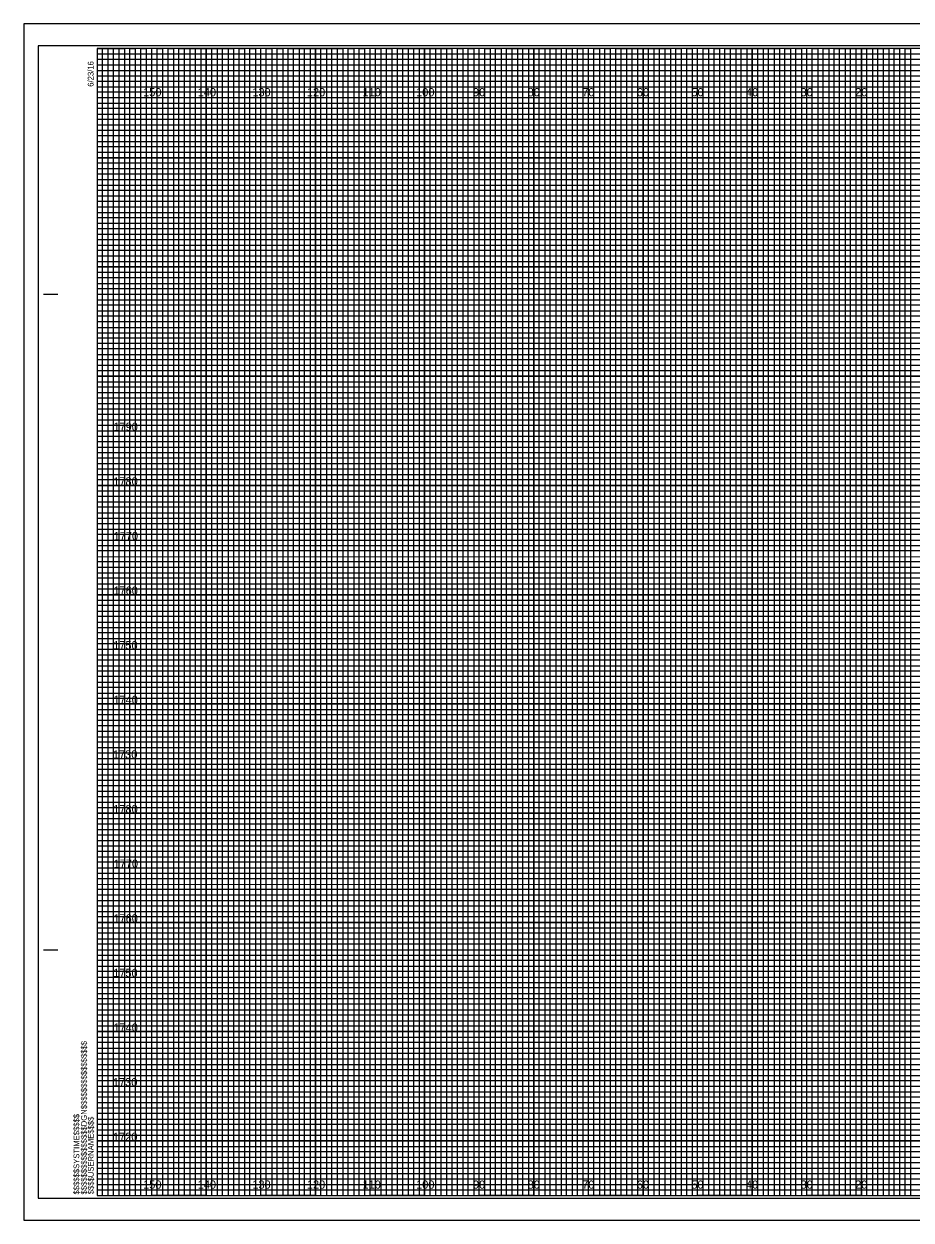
# Model space of a CAD drawing. Extents: x -15 to 323, y -5 to 6170.
# Drawn here: x -13.4 to 149.1, y 1095.5 to 1314.5 of the extents above; entities that cross this region are included whole.
import ezdxf

# ---------------------------------------------------------------- set-up
doc = ezdxf.new("R2010")
doc.units = 0
for name, color, linetype in [('Prop XS DDE', 7, 'Continuous'), ('Prop XS DDE Slope Text', 7, 'Continuous'), ('Prop XS DDE Text', 7, 'Continuous'), ('Prop XS Earthwork Shape', 7, 'Continuous'), ('Prop XS Noise Wall', 7, 'Continuous'), ('Prop XS Retaining Wall', 7, 'Continuous'), ('Prop XS Station Labels', 7, 'Continuous'), ('Scratch_Level_3', 7, 'Continuous'), ('Scratch_Level_7', 7, 'Continuous'), ('Scratch_Level_8', 7, 'Continuous'), ('Sheet Cross Section Grid Minor 1 CELL', 7, 'Continuous')]:
    doc.layers.add(name, color=color, linetype=linetype)

msp = doc.modelspace()

# ---------------------------------------------------------------- linework, layer by layer
at = {"layer": 'Prop XS DDE'}
msp.add_lwpolyline([(-13.4, 1095.5), (323.3, 1095.5), (323.3, 1314.5), (-13.4, 1314.5)], close=True, dxfattribs=at)
at = {"layer": 'Prop XS DDE Slope Text'}
msp.add_lwpolyline([(-10.8, 1099.5), (322.4, 1099.5), (322.4, 1310.5), (-10.8, 1310.5)], close=True, dxfattribs=at)
at = {"layer": 'Prop XS DDE Text'}
for p, q in [((10, 1100), (10, 1310)), ((20, 1100), (20, 1310)), ((30, 1100), (30, 1310)), ((40, 1100), (40, 1310)), ((50, 1100), (50, 1310)), ((60, 1100), (60, 1310)), ((70, 1100), (70, 1310)), ((80, 1100), (80, 1310)), ((90, 1100), (90, 1310)), ((100, 1100), (100, 1310)), ((110, 1100), (110, 1310)), ((120, 1100), (120, 1310)), ((130, 1100), (130, 1310)), ((140, 1100), (140, 1310)), ((0, 1300), (320, 1300)), ((0, 1290), (320, 1290)), ((0, 1280), (320, 1280)), ((0, 1270), (320, 1270)), ((0, 1260), (320, 1260)), ((0, 1250), (320, 1250)), ((0, 1240), (320, 1240)), ((0, 1230), (320, 1230)), ((0, 1220), (320, 1220)), ((0, 1210), (320, 1210)), ((0, 1200), (320, 1200)), ((0, 1190), (320, 1190)), ((0, 1180), (320, 1180)), ((0, 1170), (320, 1170)), ((0, 1160), (320, 1160)), ((0, 1150), (320, 1150)), ((0, 1140), (320, 1140)), ((0, 1130), (320, 1130)), ((0, 1120), (320, 1120)), ((0, 1110), (320, 1110))]:
    msp.add_line(p, q, dxfattribs=at)
at = {"layer": 'Prop XS Earthwork Shape'}
for p, q in [((10, 1310), (0, 1310)), ((10, 1100), (10, 1310)), ((30, 1310), (20, 1310)), ((20, 1310), (20, 1100)), ((30, 1100), (30, 1310)), ((50, 1310), (40, 1310)), ((40, 1310), (40, 1100)), ((50, 1100), (50, 1310)), ((70, 1310), (60, 1310)), ((60, 1310), (60, 1100)), ((70, 1100), (70, 1310)), ((90, 1310), (80, 1310)), ((80, 1310), (80, 1100)), ((90, 1100), (90, 1310)), ((110, 1310), (100, 1310)), ((100, 1310), (100, 1100)), ((110, 1100), (110, 1310)), ((130, 1310), (120, 1310)), ((120, 1310), (120, 1100)), ((130, 1100), (130, 1310)), ((150, 1310), (140, 1310)), ((140, 1310), (140, 1100)), ((20, 1100), (10, 1100)), ((40, 1100), (30, 1100)), ((60, 1100), (50, 1100)), ((80, 1100), (70, 1100)), ((100, 1100), (90, 1100)), ((120, 1100), (110, 1100)), ((140, 1100), (130, 1100))]:
    msp.add_line(p, q, dxfattribs=at)
for points in [[(0, 1300), (320, 1300), (320, 1290), (0, 1290)], [(0, 1280), (320, 1280), (320, 1270), (0, 1270)], [(0, 1260), (320, 1260), (320, 1250), (0, 1250)], [(0, 1240), (320, 1240), (320, 1230), (0, 1230)], [(0, 1220), (320, 1220), (320, 1210), (0, 1210)], [(0, 1200), (320, 1200), (320, 1190), (0, 1190)], [(0, 1180), (320, 1180), (320, 1170), (0, 1170)], [(0, 1160), (320, 1160), (320, 1150), (0, 1150)], [(0, 1140), (320, 1140), (320, 1130), (0, 1130)], [(0, 1120), (320, 1120), (320, 1110), (0, 1110)]]:
    msp.add_lwpolyline(points, dxfattribs=at)
at = {"layer": 'Prop XS Noise Wall'}
for p, q in [((-9.8, 1265), (-7.3, 1265)), ((-9.7, 1265), (-7.2, 1265)), ((-9.8, 1145), (-7.3, 1145)), ((-9.7, 1145), (-7.2, 1145)), ((0, 1100), (0, 1100)), ((0, 1100), (0, 1100)), ((0, 1100), (0, 1100)), ((0, 1100), (0, 1100)), ((0, 1100), (0, 1100)), ((0, 1100), (0, 1100)), ((0, 1100), (0, 1100))]:
    msp.add_line(p, q, dxfattribs=at)
msp.add_lwpolyline([(320, 1310), (0, 1310), (0, 1100), (320, 1100)], close=True, dxfattribs=at)
at = {"layer": 'Prop XS Retaining Wall'}
for points in [[(0, 1100), (1, 1100), (1, 1310), (2, 1310), (2, 1100)], [(2, 1100), (3, 1100), (3, 1310), (4, 1310), (4, 1100)], [(5, 1100), (6, 1100), (6, 1310), (7, 1310), (7, 1100)], [(7, 1100), (8, 1100), (8, 1310), (9, 1310), (9, 1100)], [(10, 1100), (11, 1100), (11, 1310), (12, 1310), (12, 1100)], [(12, 1100), (13, 1100), (13, 1310), (14, 1310), (14, 1100)], [(15, 1100), (16, 1100), (16, 1310), (17, 1310), (17, 1100)], [(17, 1100), (18, 1100), (18, 1310), (19, 1310), (19, 1100)], [(20, 1100), (21, 1100), (21, 1310), (22, 1310), (22, 1100)], [(22, 1100), (23, 1100), (23, 1310), (24, 1310), (24, 1100)], [(25, 1100), (26, 1100), (26, 1310), (27, 1310), (27, 1100)], [(27, 1100), (28, 1100), (28, 1310), (29, 1310), (29, 1100)], [(30, 1100), (31, 1100), (31, 1310), (32, 1310), (32, 1100)], [(32, 1100), (33, 1100), (33, 1310), (34, 1310), (34, 1100)], [(35, 1100), (36, 1100), (36, 1310), (37, 1310), (37, 1100)], [(37, 1100), (38, 1100), (38, 1310), (39, 1310), (39, 1100)], [(40, 1100), (41, 1100), (41, 1310), (42, 1310), (42, 1100)], [(42, 1100), (43, 1100), (43, 1310), (44, 1310), (44, 1100)], [(45, 1100), (46, 1100), (46, 1310), (47, 1310), (47, 1100)], [(47, 1100), (48, 1100), (48, 1310), (49, 1310), (49, 1100)], [(50, 1100), (51, 1100), (51, 1310), (52, 1310), (52, 1100)], [(52, 1100), (53, 1100), (53, 1310), (54, 1310), (54, 1100)], [(55, 1100), (56, 1100), (56, 1310), (57, 1310), (57, 1100)], [(57, 1100), (58, 1100), (58, 1310), (59, 1310), (59, 1100)], [(60, 1100), (61, 1100), (61, 1310), (62, 1310), (62, 1100)], [(62, 1100), (63, 1100), (63, 1310), (64, 1310), (64, 1100)], [(65, 1100), (66, 1100), (66, 1310), (67, 1310), (67, 1100)], [(67, 1100), (68, 1100), (68, 1310), (69, 1310), (69, 1100)], [(70, 1100), (71, 1100), (71, 1310), (72, 1310), (72, 1100)], [(72, 1100), (73, 1100), (73, 1310), (74, 1310), (74, 1100)], [(75, 1100), (76, 1100), (76, 1310), (77, 1310), (77, 1100)], [(77, 1100), (78, 1100), (78, 1310), (79, 1310), (79, 1100)], [(80, 1100), (81, 1100), (81, 1310), (82, 1310), (82, 1100)], [(82, 1100), (83, 1100), (83, 1310), (84, 1310), (84, 1100)], [(85, 1100), (86, 1100), (86, 1310), (87, 1310), (87, 1100)], [(87, 1100), (88, 1100), (88, 1310), (89, 1310), (89, 1100)], [(90, 1100), (91, 1100), (91, 1310), (92, 1310), (92, 1100)], [(92, 1100), (93, 1100), (93, 1310), (94, 1310), (94, 1100)], [(95, 1100), (96, 1100), (96, 1310), (97, 1310), (97, 1100)], [(97, 1100), (98, 1100), (98, 1310), (99, 1310), (99, 1100)], [(100, 1100), (101, 1100), (101, 1310), (102, 1310), (102, 1100)], [(102, 1100), (103, 1100), (103, 1310), (104, 1310), (104, 1100)], [(105, 1100), (106, 1100), (106, 1310), (107, 1310), (107, 1100)], [(107, 1100), (108, 1100), (108, 1310), (109, 1310), (109, 1100)], [(110, 1100), (111, 1100), (111, 1310), (112, 1310), (112, 1100)], [(112, 1100), (113, 1100), (113, 1310), (114, 1310), (114, 1100)], [(115, 1100), (116, 1100), (116, 1310), (117, 1310), (117, 1100)], [(117, 1100), (118, 1100), (118, 1310), (119, 1310), (119, 1100)], [(120, 1100), (121, 1100), (121, 1310), (122, 1310), (122, 1100)], [(122, 1100), (123, 1100), (123, 1310), (124, 1310), (124, 1100)], [(125, 1100), (126, 1100), (126, 1310), (127, 1310), (127, 1100)], [(127, 1100), (128, 1100), (128, 1310), (129, 1310), (129, 1100)], [(130, 1100), (131, 1100), (131, 1310), (132, 1310), (132, 1100)], [(132, 1100), (133, 1100), (133, 1310), (134, 1310), (134, 1100)], [(135, 1100), (136, 1100), (136, 1310), (137, 1310), (137, 1100)], [(137, 1100), (138, 1100), (138, 1310), (139, 1310), (139, 1100)], [(140, 1100), (141, 1100), (141, 1310), (142, 1310), (142, 1100)], [(142, 1100), (143, 1100), (143, 1310), (144, 1310), (144, 1100)], [(145, 1100), (146, 1100), (146, 1310), (147, 1310), (147, 1100)], [(147, 1100), (148, 1100), (148, 1310), (149, 1310), (149, 1100)]]:
    msp.add_lwpolyline(points, dxfattribs=at)
at = {"layer": 'Prop XS Station Labels'}
for points in [[(0, 1310), (5, 1310), (5, 1100), (15, 1100), (15, 1310), (25, 1310), (25, 1100), (35, 1100), (35, 1310), (45, 1310), (45, 1100), (55, 1100), (55, 1310), (65, 1310), (65, 1100), (75, 1100), (75, 1310), (85, 1310), (85, 1100), (95, 1100), (95, 1310), (105, 1310), (105, 1100), (115, 1100), (115, 1310), (125, 1310), (125, 1100), (135, 1100), (135, 1310), (145, 1310), (145, 1100), (155, 1100)], [(0, 1305), (275, 1305)], [(0, 1285), (320, 1285), (320, 1295), (0, 1295)], [(0, 1265), (320, 1265), (320, 1275), (0, 1275)], [(0, 1245), (320, 1245), (320, 1255), (0, 1255)], [(0, 1225), (320, 1225), (320, 1235), (0, 1235)], [(0, 1205), (320, 1205), (320, 1215), (0, 1215)], [(0, 1185), (320, 1185), (320, 1195), (0, 1195)], [(0, 1165), (320, 1165), (320, 1175), (0, 1175)], [(0, 1145), (320, 1145), (320, 1155), (0, 1155)], [(0, 1125), (320, 1125), (320, 1135), (0, 1135)], [(0, 1105), (320, 1105), (320, 1115), (0, 1115)]]:
    msp.add_lwpolyline(points, dxfattribs=at)
at = {"layer": 'Scratch_Level_7'}
for p, q in [((323.3, 1314.5), (-13.4, 1314.5)), ((-13.4, 1314.5), (-13.4, 1095.5)), ((-13.4, 1095.5), (323.3, 1095.5))]:
    msp.add_line(p, q, dxfattribs=at)
at = {"layer": 'Sheet Cross Section Grid Minor 1 CELL'}
for p, q in [((0, 1309), (260, 1309)), ((260, 1307.98), (0, 1307.98)), ((0, 1307.98), (0, 1307)), ((0, 1307), (260, 1307)), ((260, 1305.89), (0, 1305.89)), ((0, 1305.89), (0, 1304)), ((0, 1304), (320, 1304))]:
    msp.add_line(p, q, dxfattribs=at)
for points in [[(0, 1303), (270, 1303), (320, 1303), (320, 1302), (0, 1302)], [(0, 1301), (320, 1301), (320, 1299), (0, 1299)], [(0, 1298), (320, 1298), (320, 1297), (0, 1296.98)], [(0, 1296), (320, 1296), (320, 1294), (0, 1294)], [(0, 1293), (320, 1293), (320, 1292), (0, 1292)], [(0, 1291), (320, 1291), (320, 1289), (0, 1289)], [(0, 1288), (320, 1288), (320, 1287), (0, 1287)], [(0, 1286), (320, 1286), (320, 1284), (0, 1284)], [(0, 1283), (320, 1283), (320, 1282), (0, 1282)], [(0, 1281), (320, 1281), (320, 1279), (0, 1279)], [(0, 1278), (320, 1278), (320, 1277), (0, 1277)], [(0, 1276), (320, 1276), (320, 1273.95), (320, 1273), (320, 1272), (0, 1272)], [(0, 1274), (320, 1274), (320, 1273), (0, 1273)], [(0, 1271), (320, 1271), (320, 1269), (0, 1269.03)], [(0, 1269.03), (320, 1269), (320, 1268), (0, 1268)], [(0, 1267), (320, 1267), (320, 1266), (0, 1266)], [(0, 1264), (320, 1264), (320, 1263), (0, 1263)], [(0, 1262), (320, 1262), (320, 1261), (0, 1261)], [(-0.07, 1258.89), (320, 1258.89), (320, 1257.88), (-0.07, 1257.88)], [(0, 1257), (320, 1257), (320, 1256), (0, 1256)], [(0, 1254), (320, 1254), (320, 1253), (0, 1253)], [(0, 1252), (320, 1252), (320, 1251), (0, 1251)], [(0, 1249), (320, 1249), (320, 1248), (0, 1248)], [(0, 1247), (320, 1247), (320, 1246), (0, 1246)], [(0, 1244), (320, 1244), (320, 1243), (0, 1243)], [(0, 1242), (320, 1242), (320, 1241), (0, 1241)], [(0, 1239), (320, 1239), (319.99, 1237.98), (0, 1238)], [(0, 1237), (320, 1237), (320, 1236), (0, 1236)], [(0, 1234), (320, 1234), (320, 1233), (0, 1233)], [(0, 1232), (320, 1232), (320, 1231), (0, 1231)], [(0, 1229), (320, 1229), (320, 1228), (0, 1228)], [(0, 1227), (320, 1227), (320, 1226), (0, 1226)], [(0, 1224), (320, 1224), (320, 1223), (0, 1223)], [(0, 1222), (320, 1222), (320, 1221), (0, 1221)], [(0, 1219), (320, 1219), (320, 1218), (0, 1218)], [(0, 1216.99), (320.07, 1216.91), (320, 1216), (0, 1216)], [(0, 1214), (320, 1214), (320, 1213), (0, 1213)], [(0, 1212), (320, 1212), (320, 1211), (0, 1211)], [(0, 1209), (320, 1209), (320, 1208), (0, 1208)], [(0, 1207), (320, 1207), (320, 1206), (0, 1206)], [(0, 1204), (320, 1204), (320, 1203), (0, 1203)], [(0, 1202), (320, 1202), (320, 1201), (0, 1201)], [(0, 1199), (320, 1199), (320, 1198), (0, 1198)], [(0, 1197), (320, 1197), (320, 1196), (0, 1196)], [(0, 1194), (320, 1194), (320, 1193), (0, 1193)], [(0, 1192), (320, 1192), (320, 1191), (0, 1191)], [(0, 1189), (320, 1189), (320, 1188), (0, 1188)], [(0, 1187), (320, 1187), (320, 1186), (0, 1186)], [(0, 1184), (320, 1184), (320, 1183), (0, 1183)], [(0, 1182), (320, 1182), (320, 1181), (0, 1181)], [(0, 1179), (320, 1179), (319.99, 1177.98), (0, 1178)], [(0, 1177), (320, 1177), (320, 1176), (0, 1176)], [(0, 1174), (320, 1174), (320, 1173), (0, 1173)], [(0, 1172), (320, 1172), (320, 1171), (0, 1171)], [(0, 1169), (320, 1169), (320, 1168), (0, 1168)], [(0, 1167), (320, 1167), (320, 1166), (0, 1166)], [(0, 1164), (320, 1164), (320, 1163), (0, 1163)], [(0, 1162), (320, 1162), (320, 1161), (0, 1161)], [(0, 1159), (320, 1159), (320, 1158), (0, 1158)], [(0, 1156.99), (320.07, 1156.91), (320, 1156), (0, 1156)], [(0, 1154), (320, 1154), (320, 1153), (0, 1153)], [(0, 1152), (320, 1152), (320, 1151), (0, 1151)], [(0, 1149), (320, 1149), (320, 1148), (0, 1148)], [(0, 1147), (320, 1147), (320, 1146), (0, 1146)], [(0, 1144), (320, 1144), (320, 1143), (0, 1143)], [(0, 1142), (320, 1142), (320, 1141), (0, 1141)], [(0, 1139), (320, 1139), (320, 1138), (0, 1138)], [(0, 1137), (320, 1137), (320, 1136), (0, 1136)], [(0, 1134), (320, 1134), (320, 1133), (0, 1133)], [(0, 1132), (320, 1132), (320, 1131), (0, 1131)], [(0, 1129), (320, 1129), (320, 1128), (0, 1128)], [(0, 1127), (320, 1127), (320, 1126), (0, 1126)], [(0, 1124), (320, 1124), (320, 1123), (0, 1123)], [(0, 1122), (320, 1122), (320, 1121), (0, 1121)], [(0, 1119), (320, 1119), (320, 1118), (0, 1118)], [(0, 1117), (320, 1117), (320, 1116), (0, 1116)], [(0, 1114), (320, 1114), (320, 1113), (0, 1113)], [(0, 1112), (320, 1112), (320, 1111), (0, 1111)], [(0, 1109), (320, 1109), (320, 1108), (0, 1108)], [(0, 1107), (320, 1107), (320, 1106), (0, 1106)], [(0, 1104), (320, 1104), (320, 1103), (0, 1103)], [(0, 1102), (320, 1102), (320, 1101), (0, 1101)]]:
    msp.add_lwpolyline(points, dxfattribs=at)

# ---------------------------------------------------------------- texts
at = {"layer": 'Prop XS Noise Wall'}
for s, p in [('6/23/16', (-0.65, 1303)), ('$$$$$$$$$$$$$$$$DGN$$$$$$$$$$$$$$$$', (-1.88, 1100.18)), ('$$$$$$SYSTIME$$$$$', (-3.26, 1100.18)), ('$$$$USERNAME$$$$', (-0.62, 1100.23))]:
    msp.add_text(s, height=1.05, rotation=90, dxfattribs=at).set_placement(p)
at = {"layer": 'Scratch_Level_3'}
for s, p in [('1790', (3, 1240)), ('1780', (2.98, 1230)), ('1770', (3.04, 1220)), ('1760', (3, 1210)), ('1750', (2.96, 1200)), ('1740', (3, 1190)), ('1730', (2.92, 1180)), ('1780', (2.98, 1170)), ('1770', (3.04, 1160)), ('1760', (3, 1150)), ('1750', (2.96, 1140)), ('1740', (3, 1130)), ('1730', (2.92, 1120)), ('1720', (2.93, 1110))]:
    msp.add_text(s, height=1.5, dxfattribs=at).set_placement(p)
at = {"layer": 'Scratch_Level_8'}
for s, p in [('150', (8.44, 1301.25)), ('140', (18.44, 1301.25)), ('130', (28.44, 1301.25)), ('120', (38.44, 1301.25)), ('110', (48.62, 1301.25)), ('100', (58.44, 1301.25)), ('90', (68.86, 1301.25)), ('80', (78.86, 1301.25)), ('70', (88.86, 1301.25)), ('60', (98.86, 1301.25)), ('50', (108.86, 1301.25)), ('40', (118.86, 1301.25)), ('30', (128.86, 1301.25)), ('20', (138.86, 1301.25)), ('150', (8.44, 1101.25)), ('140', (18.44, 1101.25)), ('130', (28.44, 1101.25)), ('120', (38.44, 1101.25)), ('110', (48.62, 1101.25)), ('100', (58.44, 1101.25)), ('90', (68.86, 1101.25)), ('80', (78.86, 1101.25)), ('70', (88.86, 1101.25)), ('60', (98.86, 1101.25)), ('50', (108.86, 1101.25)), ('40', (118.86, 1101.25)), ('30', (128.86, 1101.25)), ('20', (138.86, 1101.25))]:
    msp.add_text(s, height=1.5, dxfattribs=at).set_placement(p)

doc.saveas('drawing.dxf')
